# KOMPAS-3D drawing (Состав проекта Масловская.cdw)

Referenced files in C:\Users\Admin\Desktop\: Состав проекта.cdw
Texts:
  125 1 126 1 127 1 128 0 50 1|SPDS|125 1 126 1 127 1 128 0 50 1
  129 1 130 1 131 1 132 0 50 1|SPDS|129 1 130 1 131 1 132 0 50 1
  Номер
  раздела
  Мероприятия по обеспечению пожарной
  безопасности
  Подраздел 9.1 Противопожарные мероприятия
  Подраздел 8.1 Охрана окружающей среды
  Перечень мероприятий по охране окружающей
  среды
  Проект организации работ по сносу или
  демонтажу объектов капитального
  строительства
  Проект организации строительства
  Подраздел 5.4  АИИСКУЭ
  Подраздел 5.3 Телемиханика
  Подраздел 5.2 РЗА, монтажные схемы,
  кабельное хозяйство
  Подраздел 5.1 Электротехнические решения
  Сведения об инженерном оборудовании, о сетях
  инженерно-технического обеспечения,
  перечень инженерно-технических мероприятий,
  содержание технологических решений
  Подраздел 4.2.    Маслосборник
  Подраздел 4.1  Строительные решения
  Конструктивные и объёмно-планировочные
  решения
  Архитектурные решения
  Схема планировочной организации
  земельного участка
  Пояснительная записка
  техническим
  заданием
  не предусмотрено
  Охрана труда
  Мероприятия по обеспечению
  электромагнитной совместимости
  Подраздел 12.1 Сборник спецификаций и заданий
  заводам-изготовителям
  Иная документация в случаях
  предусмотренных федеральными законами
  Смета на строительство объектов
  капитального строительства
  Мероприятия по обеспечению доступа инвалидов
  Инженер
  Состав проекта
  Щукин
  ТЭЛПРО Инжиниринг Тула
  филиал ООО "ТЭЛПРО Инжиниринг"
  Проектирование реконструкции ПС 35кВ Масловская
  с заменой трансформаторов 4 и 6,3 МВА на 2x10 МВА
  ГИП
  Якушев
  Вед.инженер
  Гурьянов
  Рабочие чертежи основного комплекта. ГОСТ Р 21.1101-2009 Ф3
  Лит-Масса-Масштаб
  Материал-Предприятие
  Стадия
  Лист
  Листов
  Изм.
  Кол.уч.
  №док.
  Подп.
  Дата
  Изменение
  Номер документа
  Подпись
  Наименование объекта строительства, в состав которого входит здание, наим. микр
  Наименование здания (сооружения)
  Порядковый номер листа
  Количество листов в документе
  Наименование изображения
  Индекс предприятия, выпускающего документ
  Инв. № подл.
  Подп. и дата
  Взам. инв. №
  Инвентарный номер подлинника
  Подпись принявшего подлинник на хранение
  Инвентарный номер подлинника, взамен которого выпущен данный подлинник
  Согласовано
  Формат листа
  Согласование
  03 Рабочие чертежи основного комплекта. ГОСТ Р 21.1101-2009 Ф3
  филиал ООО "ТЭЛПРО Инжинжиниринг"
  Чертежи строительных изделий. Посл. листы. ГОСТ Р 21.1101-2009 Ф6
  Порядковый номер документа
  05 Чертежи строительных изделий. Посл. листы. ГОСТ Р 21.1101-2009 Ф6
Dimensions and other numbers on the sheet: 11-В; 9; 8; 7; 6; 5; 4; 3; 2; 1; 11-В-ПБ; 11-В-ООС; 11-В-ПОС; 11-В-ИОС1.4; 11-В-ИОС1.3; 11-В-ИОС1.2; 11-В-ИОС1.1; 11-В-КР1; 11-В-КР; 11-В-ПЗ; 12.2; 13; 12; 11; 10; 11-В-ОТ; 11-В-ЭМС; 11-В-СС; 11-В-СМ; 11-В-; 1/2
